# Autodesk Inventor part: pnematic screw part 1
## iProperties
Created: 2010-02
Part Number: pnematic screw part 1
Document SubType Name: Modeling
Designer: clee1
Density: 1 g/cm^3
Author: clee1
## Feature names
1. Extrusion1
2. Extrusion2
3. Extrusion3
